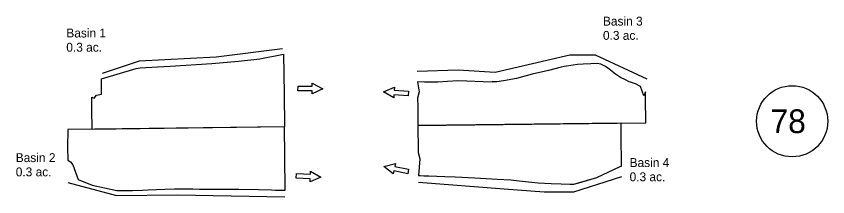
# Model space of a CAD drawing. Extents: x 23468265 to 23469086, y 6738070 to 6738253.
import ezdxf

# ---------------------------------------------------------------- set-up
doc = ezdxf.new("R2010")
doc.units = 0
for name, color, linetype in [('CorridorGraphics', 7, 'Continuous'), ('MeshTop', 7, 'Continuous'), ('TC_Grading', 7, 'Continuous'), ('Terrain', 7, 'Continuous'), ('TL_Grading', 7, 'Continuous'), ('TL_GroundIntercept', 7, 'Continuous')]:
    doc.layers.add(name, color=color, linetype=linetype)

msp = doc.modelspace()

# ---------------------------------------------------------------- linework, layer by layer
at = {"layer": 'CorridorGraphics'}
msp.add_lwpolyline([(23468317.31, 6738120.18), (23468317.47, 6738107.11), (23468320.25, 6738105.74), (23468322.58, 6738102.65), (23468328, 6738087.74), (23468342.15, 6738081.91), (23468367.19, 6738076.52), (23468378.58, 6738076.5), (23468383.06, 6738076.69), (23468393.06, 6738077.07), (23468398.95, 6738077.29), (23468415.77, 6738077.94), (23468425.3, 6738078.24), (23468435.29, 6738078.26), (23468443.94, 6738078.16), (23468450.56, 6738077.96), (23468466.04, 6738077.78), (23468478.38, 6738077.84), (23468490.57, 6738077.88), (23468510.41, 6738077.55), (23468523.42, 6738077.09), (23468527.7, 6738076.93), (23468537.34, 6738076.99), (23468536.94, 6738111.07), (23468536.57, 6738140.83), (23468317.43, 6738138.2)], close=True, dxfattribs=at)
at = {"layer": 'MeshTop'}
for p, q in [((23468550.28, 6738177.37), (23468550.32, 6738182.14)), ((23468550.32, 6738182.14), (23468564.64, 6738182.02)), ((23468564.64, 6738182.02), (23468564.66, 6738185)), ((23468564.66, 6738185), (23468575.35, 6738179.55)), ((23468576.65, 6738182.27), (23468576.65, 6738182.28)), ((23468576.65, 6738182.28), (23468576.66, 6738182.27)), ((23468576.65, 6738182.24), (23468576.65, 6738182.27)), ((23468576.65, 6738182.27), (23468576.65, 6738182.27)), ((23468576.66, 6738182.24), (23468576.65, 6738182.24)), ((23468576.66, 6738182.27), (23468576.66, 6738182.27)), ((23468576.66, 6738182.27), (23468576.66, 6738182.24)), ((23468564.6, 6738177.25), (23468550.28, 6738177.37)), ((23468575.35, 6738179.55), (23468564.57, 6738174.27)), ((23468564.57, 6738174.27), (23468564.6, 6738177.25)), ((23468636.79, 6738176.5), (23468647.89, 6738181.06)), ((23468647.09, 6738170.35), (23468636.79, 6738176.5)), ((23468647.31, 6738173.33), (23468647.09, 6738170.35)), ((23468661.59, 6738172.26), (23468647.31, 6738173.33)), ((23468647.89, 6738181.06), (23468647.67, 6738178.08)), ((23468647.67, 6738178.08), (23468661.94, 6738177.02)), ((23468661.94, 6738177.02), (23468661.59, 6738172.26)), ((23468637.2, 6738100.76), (23468648.78, 6738103.93)), ((23468646.68, 6738093.4), (23468637.2, 6738100.76)), ((23468648.78, 6738103.93), (23468648.2, 6738101)), ((23468648.2, 6738101), (23468662.23, 6738098.2)), ((23468548.39, 6738089.07), (23468548.64, 6738093.83)), ((23468548.64, 6738093.83), (23468562.93, 6738093.08)), ((23468562.93, 6738093.08), (23468563.09, 6738096.05)), ((23468563.09, 6738096.05), (23468573.53, 6738090.13)), ((23468647.26, 6738096.32), (23468646.68, 6738093.4)), ((23468661.3, 6738093.52), (23468647.26, 6738096.32)), ((23468662.23, 6738098.2), (23468661.3, 6738093.52)), ((23468562.68, 6738088.31), (23468548.39, 6738089.07)), ((23468573.53, 6738090.13), (23468562.52, 6738085.33)), ((23468562.52, 6738085.33), (23468562.68, 6738088.31))]:
    msp.add_line(p, q, dxfattribs=at)
for points in [[(23468534.59, 6738219.97), (23468467.64, 6738211.63), (23468389.67, 6738207.59), (23468352.22, 6738194.8)], [(23468903.38, 6738189.16), (23468851.22, 6738213.65), (23468825.14, 6738213.38), (23468749.62, 6738196.01), (23468712.27, 6738198.27), (23468670.94, 6738196.99)], [(23468317.57, 6738084.52), (23468366.78, 6738071.6), (23468428.39, 6738072.29), (23468536.97, 6738070.22)], [(23468672.06, 6738085.07), (23468758.66, 6738078.3), (23468799.41, 6738075.11), (23468829.35, 6738075.3), (23468877.69, 6738090.66)]]:
    msp.add_lwpolyline(points, dxfattribs=at)
at = {"layer": 'TC_Grading'}
msp.add_lwpolyline([(23468829.17, 6738083.01), (23468852.42, 6738089.67), (23468875.96, 6738100.75), (23468877.51, 6738101.07), (23468877.22, 6738132.89), (23468877.11, 6738144.84), (23468671.58, 6738142.41), (23468671.88, 6738116.63), (23468671.9, 6738114.87), (23468673.58, 6738108.49), (23468672.18, 6738091.61), (23468673.82, 6738091.64), (23468677.53, 6738091.54), (23468682.61, 6738091.43), (23468698.9, 6738090.83), (23468709.29, 6738090.25), (23468729.02, 6738089.38), (23468746.34, 6738088.46), (23468751.76, 6738088.19), (23468765.58, 6738087.22), (23468773.88, 6738086.51), (23468789.82, 6738084.69), (23468793.1, 6738084.33), (23468806.38, 6738083.49), (23468816.57, 6738083.21), (23468825.36, 6738083.07), (23468829.23, 6738083.01), (23468834.33, 6738084.49), (23468852.4, 6738089.66)], dxfattribs=at)
at = {"layer": 'Terrain'}
msp.add_lwpolyline([(23468341.86, 6738158.89), (23468341.71, 6738171.12), (23468344.34, 6738170.13), (23468346.68, 6738173.04), (23468351.56, 6738174.19), (23468351.5, 6738189.6), (23468386.76, 6738199.92), (23468390.69, 6738200.73), (23468408.14, 6738201.78), (23468421.18, 6738202.27), (23468463.24, 6738205.09), (23468490.06, 6738207.53), (23468511.76, 6738209.95), (23468535.72, 6738214.35), (23468536.19, 6738174.38), (23468536.57, 6738140.83), (23468342.18, 6738138.37)], close=True, dxfattribs=at)
at = {"layer": 'TL_Grading'}
msp.add_lwpolyline([(23468819.33, 6738201.89), (23468816.36, 6738201.35), (23468803.61, 6738197.88), (23468787.28, 6738194.27), (23468771.4, 6738189.86), (23468758.3, 6738187.68), (23468751.52, 6738186.64), (23468746.83, 6738186.61), (23468746.83, 6738186.61), (23468746.56, 6738186.06), (23468737.74, 6738186.44), (23468721.01, 6738187.24), (23468711.8, 6738187.6), (23468701.39, 6738186.83), (23468691.64, 6738186.11), (23468685.5, 6738186.07), (23468678.26, 6738186.26), (23468671.06, 6738186.39), (23468672.77, 6738176.36), (23468671.17, 6738169.92), (23468671.35, 6738161.87), (23468671.58, 6738142.41), (23468902.06, 6738145.13), (23468901.76, 6738170.42), (23468901.69, 6738176.29), (23468900.11, 6738172.42), (23468896.64, 6738181.68), (23468891.58, 6738184.34), (23468886.58, 6738186.33), (23468885.13, 6738186.58), (23468881.54, 6738188.61), (23468876.52, 6738190.78), (23468871.41, 6738194.42), (23468866.37, 6738198.23), (23468863.55, 6738200.34), (23468861.44, 6738201.91), (23468856.44, 6738204.39), (23468852.87, 6738205.14), (23468846.47, 6738204.77), (23468838.66, 6738204.33), (23468832.9, 6738204), (23468828.5, 6738203.29), (23468819.36, 6738201.89), (23468819.33, 6738201.89)], dxfattribs=at)
at = {"layer": 'TL_GroundIntercept'}
msp.add_circle((23469050.08, 6738146.62), 36, dxfattribs=at)

# ---------------------------------------------------------------- texts
at = {"layer": 'TC_Grading'}
for s, p in [('Basin 3', (23468858.72, 6738243.41)), ('Basin 1', (23468316.02, 6738231.41)), ('0.3 ac.', (23468858.72, 6738229.01)), ('0.3 ac.', (23468316.02, 6738217.01)), ('Basin 2', (23468264.89, 6738105.31)), ('Basin 4', (23468885.69, 6738100.34)), ('0.3 ac.', (23468264.89, 6738090.91)), ('0.3 ac.', (23468885.69, 6738085.94))]:
    msp.add_text(s, height=9, dxfattribs=at).set_placement(p)
at = {"layer": 'TL_GroundIntercept'}
msp.add_text('78', height=24, dxfattribs=at).set_placement((23469028.19, 6738134.62))

doc.saveas('drawing.dxf')
